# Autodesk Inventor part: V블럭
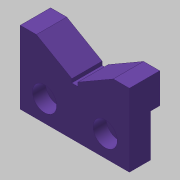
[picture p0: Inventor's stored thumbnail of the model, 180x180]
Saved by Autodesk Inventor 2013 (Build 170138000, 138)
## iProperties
Created: 2020-03
Part Number: V블럭
Material: 알루미늄 6061
Document SubType Name: Modeling
Designer: mduedu
Density: 1 g/cm^3
Author: mduedu
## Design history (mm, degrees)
sketch "스케치1"
  geometry: L1 (-18, 0)-(18, 0); L2 (18, 0)-(18, 24); L3 (-18, 24)-(-18, 0); L4 (-12.679, 24)-(-1, 17.257); L5 (1, 17.257)-(12.679, 24); L6 (1, 17.257)-(1, 16); L7 (1, 16)-(-1, 16); L8 (-1, 16)-(-1, 17.257); L9 (18, 24)-(12.679, 24); L10 (-12.679, 24)-(-18, 24); L11 (0, 0)-(0, 16); C1 r 15 at (0, 34); 1 further point
  constraints: 22 end point, 4 parallel, 3 vertical, 2 horizontal, 2 midpoint, 1 centre point, 1 coincident, 1 collinear, 1 equal length, 1 horizontal alignment, 1 perpendicular, 1 tangent, 1 vertical alignment
  dimensions: "d0" = 36 distance of L1.start L1.end; "d2" = 24 distance of L1.end L2.end; "d3" = 2 distance of L6.end L7.end; "d5" = 8 distance from line of L7 L2.end; "d6" = 120 deg angle of L5 L4; "d7" = 30 diameter of C1; "d8" = 34 distance from line of C1.centre L1
extrude "돌출1" new body sketch "스케치1" distance "d9" = 10; taper "d10" = 0 deg
sketch "스케치2"
  geometry: L1 (0, 0)-(-3, 0); L2 (-3, 0)-(-3, 14); L3 (-3, 14)-(0, 14); L4 (0, 14)-(0, 0)
  constraints: 8 end point, 2 parallel, 1 horizontal, 1 perpendicular
  dimensions: "d11" = 3 distance of L2.end L3.end; "d12" = 14 distance of L1.end L2.end
extrude "돌출2" cut sketch "스케치2" stored distance "d13" = 10; taper "d14" = 0 deg
sketch "스케치3"
  geometry: L1 (-18, 0)-(18, 0) reference; 3 further points
  constraints: 1 horizontal alignment
  dimensions: "d15" = 10 horizontal distance of point (-10, 7) point (0, 0); "d16" = 20 distance of point (10, 7) point (-10, 7); "d17" = 7 distance from line of point (10, 7) L1
hole "구멍1" sketch "스케치3" at (-10, 7), (10, 7) diameter "d18" = 4.5; stored, may be unused: countersink angle "d22" = 90 deg, drill point angle "d24" = 118 deg; dims "d19" = 6, "d20" = 8, "d21" = 4.4, "d23" = 8
node "솔리드1"
